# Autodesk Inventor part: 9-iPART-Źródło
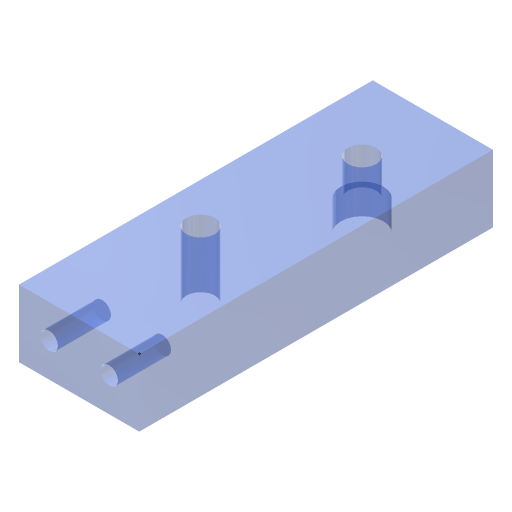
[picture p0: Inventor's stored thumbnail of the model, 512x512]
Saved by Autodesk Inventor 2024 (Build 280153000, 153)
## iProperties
Category: TEST
Company: ATC
Created: 2023-03
Part Number: 9-iPART-Źródło
Document SubType Name: Modeling
Designer: Andrzej Jaskulski
Manufacturer: Standard
Standards Organization: Custom
Material: AJ-PL-1
Density: 0.001 g/cm^3
Appearance: Niebieski (jasny)
Checked By: A.J.
Engr Approved By: Andrzej Jaskulski
Mfg Approved By: Andrzej Jaskulski
Authority: A.J.
Szer: 38,00000 mm
Wys: 68,00000 mm
Dlug: 200,00000 mm
FiStd: 16,00000 mm
m3: m3
Title: A.J.: Kurs R2024-MEP
Author: Andrzej Jaskulski
Revision Number: 1/24
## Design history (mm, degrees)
sketch "Szkic CZOŁA"
  geometry: L1 (68, 0)-(68, -38); L2 (68, -38)-(0, -38); L3 (68, 0)-(0, 0); L4 (0, 0)-(0, -38); C1 r 5 at (17, -19); C2 r 5 at (51, -19)
  constraints: 8 end point, 2 centre point, 2 horizontal, 2 vertical, 1 horizontal alignment, 1 other
  dimensions: "d1" = 38 distance of L1.start L1.end (= Szer); "d2" = 19 distance from line of C2.centre L2 (= 0.5 x d1); "d32" = 68 distance of L1.start L3.end (= Wys); "d33" = 17 distance from line of C2.centre L1 (= 0.25 x d32); "d34" = 34 distance of C1.centre C2.centre (= 0.5 x d32)
extrude "Baza" new body sketch "Szkic CZOŁA" distance "d3" = 200 (= Dlug); taper "d4" = 0 deg
extrude "Otw. w CZOLE 1" cut sketch "Szkic CZOŁA" distance "d43" = 30; taper "d44" = 0 deg
sketch "Szkic1"
  geometry: L1 (0, 0)-(0, 200) reference; L2 (68, 0)-(0, 0) reference; L3 (68, 200)-(0, 200) reference; 1 further point
  dimensions: "d90" = 45.33333 distance from line of point (45.333, 80) L1 (= 0.666667 x d32); "d91" = 80 distance from line of L2 point (45.333, 80)
hole "Otwory PROSTE" sketch "Szkic1" diameter "d93" = 16 (= FiStd); stored, may be unused: countersink angle "d97" = 90 deg, drill point angle "d99" = 118 deg; dims "d94" = 6, "d95" = 4, "d96" = 2, "d98" = 8
sketch "Szkic2"
  geometry: L1 (14.131, 113.514)-(2.685, 125.587); L2 (2.685, 125.587)-(14.131, 136.439); L3 (68, 0)-(0, 0) reference; 2 further points
  constraints: 4 end point, 1 midpoint, 1 perpendicular, 1 vertical alignment
  dimensions: "d101" = 160 distance from line of point (34, 160) L3
hole "Otw. z POGL." sketch "Szkic2" diameter "d75" = 16 (= FiStd); stored, may be unused: countersink angle "d79" = 90 deg, drill point angle "d81" = 0 deg; dims "d76" = 6, "d77" = 24 (= 1.5 x FiStd), "d78" = 17 (= d33), "d80" = 17 (= d33)
node "Bryła1"
node "Korpusy bryłowe"
node "Korpusy powierzchniowe"
other parameters: "FiStd" = 16 [user parameter; used in 3 equation terms], "Szer" = 38 [user parameter; used in 1 equation term], "Wys" = 68 [user parameter; used in 1 equation term], "Dlug" = 200 [user parameter; used in 1 equation term], "d82" = 0
